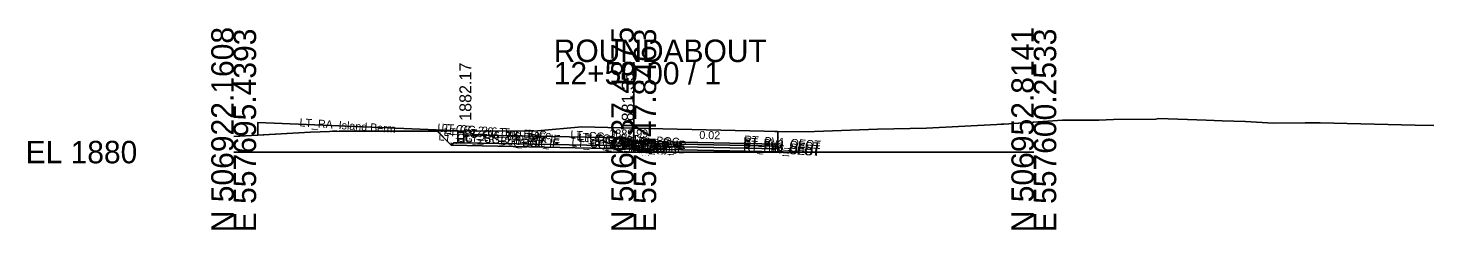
# Model space of a CAD drawing. Extents: x -36 to 140, y -10 to 2515.
# Drawn here: x -35.7 to 140, y 2490.3 to 2515.5 of the extents above; entities that cross this region are included whole.
import ezdxf

# ---------------------------------------------------------------- set-up
doc = ezdxf.new("R2010")
doc.units = 0
for name, color, linetype in [('Default', 7, 'Continuous'), ('Exist Cross Section Cell', 7, 'Continuous'), ('Exist XS Center Line Elevation Label', 7, 'Continuous'), ('Exist XS Ground Line', 7, 'Continuous'), ('Prop CMT Conc Surface', 7, 'Continuous'), ('Prop CMT Pvmt Course 1', 7, 'Continuous'), ('Prop CMT Pvmt Course 1 CG', 7, 'Continuous'), ('Prop CMT Pvmt Course 2', 7, 'Continuous'), ('Prop CMT Pvmt Course 3', 7, 'Continuous'), ('Prop CMT Pvmt Course 4', 7, 'Continuous'), ('Prop CMT Slope Grass', 7, 'Continuous'), ('Prop CMT Subgrade Earthwork', 7, 'Continuous'), ('Prop Conc 4in Sidewalk', 7, 'Continuous'), ('Prop XS Earthwork Shape', 7, 'Continuous'), ('Prop XS Finish Grade Earthwork', 7, 'Continuous'), ('Prop XS Hydro Elevations', 7, 'Continuous'), ('Typical Structure Recommendation Sheet 1 CELL', 7, 'Continuous')]:
    doc.layers.add(name, color=color, linetype=linetype)

msp = doc.modelspace()

# ---------------------------------------------------------------- linework, layer by layer
at = {"layer": 'Exist Cross Section Cell'}
for p, q in [((40, 2500), (40, 2511.23)), ((-10, 2500), (40, 2500)), ((40, 2500), (90, 2500))]:
    msp.add_line(p, q, dxfattribs=at)
at = {"layer": 'Exist XS Ground Line'}
for p, q in [((86.24, 2503.5), (93.59, 2503.98)), ((93.59, 2503.98), (98.14, 2503.98)), ((98.14, 2503.98), (99.96, 2504.06)), ((99.96, 2504.06), (105.26, 2504.12)), ((105.26, 2504.12), (105.57, 2504.18)), ((105.57, 2504.18), (109.2, 2504.05)), ((109.2, 2504.05), (111.56, 2503.96)), ((111.56, 2503.96), (113.54, 2503.88)), ((113.54, 2503.88), (116.46, 2503.8)), ((116.46, 2503.8), (119.9, 2503.59)), ((119.9, 2503.59), (123.93, 2503.63)), ((123.93, 2503.63), (125.77, 2503.65)), ((125.77, 2503.65), (137.66, 2503.35)), ((70.45, 2502.84), (76.6, 2502.97)), ((85.39, 2503.44), (85.9, 2503.48)), ((85.9, 2503.48), (86.24, 2503.5)), ((137.66, 2503.35), (140, 2503.31))]:
    msp.add_line(p, q, dxfattribs=at)
msp.add_lwpolyline([(-10, 2501.94), (-0.39, 2502.47), (3.19, 2502.62), (27.96, 2502.63), (33.49, 2503.14), (40, 2502.99), (56.29, 2502.61), (58.94, 2502.54), (62.57, 2502.57), (70.45, 2502.84), (76.6, 2502.97), (85.39, 2503.44), (85.9, 2503.48), (86.24, 2503.5), (90, 2503.74)], dxfattribs=at)
at = {"layer": 'Prop CMT Conc Surface'}
for p, q in [((18.65, 2502.45), (18, 2502.67)), ((18, 2502.67), (18, 2501.67)), ((18.75, 2501.67), (18.75, 2502.31)), ((17.2, 2500.87), (17.5, 2501.17)), ((18, 2501.17), (17.5, 2501.17)), ((18, 2501.67), (18.75, 2501.67)), ((18, 2501.67), (18, 2501.17)), ((18, 2501.17), (18.75, 2501.17)), ((18.75, 2501.17), (18.75, 2501.67)), ((38.5, 2500.76), (38.5, 2501.76)), ((39.18, 2501.53), (38.5, 2501.76)), ((40, 2500.76), (38.5, 2500.76)), ((38.59, 2500.97), (38.51, 2500.95)), ((38.51, 2500.95), (38.55, 2500.84)), ((38.55, 2500.84), (38.59, 2500.97)), ((38.64, 2501.59), (38.56, 2501.59)), ((38.56, 2501.59), (38.64, 2501.5)), ((38.64, 2501.5), (38.64, 2501.59)), ((38.84, 2501.28), (38.88, 2501.13)), ((38.92, 2501.22), (38.84, 2501.28)), ((38.88, 2501.13), (38.92, 2501.22)), ((39.15, 2500.99), (39.24, 2500.94)), ((39.18, 2500.86), (39.15, 2500.99)), ((39.24, 2500.94), (39.18, 2500.86)), ((39.25, 2501.43), (39.25, 2501.44)), ((40, 2501.34), (39.34, 2501.34)), ((39.5, 2500.95), (39.43, 2500.94)), ((39.43, 2500.94), (39.47, 2500.83)), ((39.47, 2500.83), (39.5, 2500.95)), ((39.76, 2501.27), (39.8, 2501.12)), ((39.84, 2501.21), (39.76, 2501.27)), ((39.8, 2501.12), (39.84, 2501.21)), ((40, 2501.34), (40, 2500.76)), ((40, 2500.76), (40, 2501.33))]:
    msp.add_line(p, q, dxfattribs=at)
msp.add_lwpolyline([(40, 2500.76), (40, 2501.35)], dxfattribs=at)
msp.add_lwpolyline([(40, 2500.76), (40, 2501.35)], dxfattribs=at)
for centre in [(38.57, 2501.35), (38.58, 2501.24), (38.62, 2500.87), (38.64, 2501.08), (38.71, 2501.67), (38.73, 2501.22), (38.73, 2501.39), (38.76, 2500.83), (38.78, 2501.09), (38.79, 2501), (38.85, 2501.34), (38.92, 2501.48), (38.92, 2501.06), (39.02, 2501.21), (39.02, 2500.81), (39.04, 2500.93), (39.04, 2501.34), (39.06, 2501.5), (39.07, 2501.07), (39.11, 2501.25), (39.23, 2501.28), (39.25, 2501.18), (39.27, 2500.8), (39.34, 2500.94), (39.34, 2500.79), (39.36, 2501.02), (39.37, 2501.26), (39.38, 2501.23), (39.5, 2501.22), (39.54, 2500.85), (39.56, 2501.06), (39.65, 2501.21), (39.68, 2500.81), (39.69, 2501.08), (39.71, 2500.98), (39.77, 2501.32), (39.84, 2501.05), (39.94, 2501.19), (39.94, 2500.79), (39.96, 2500.91), (39.99, 2501.05)]:
    msp.add_circle(centre, 0.00635, dxfattribs=at)
for centre, radius, start, end in [((18.6, 2502.31), 0.146, 0, 71.5651), ((38.53, 2500.76), 0.00635, 27.0386, 154.2416), ((39.15, 2501.44), 0.0937, 0, 71.5651), ((39.34, 2501.43), 0.0937, 180, 270)]:
    msp.add_arc(centre, radius, start, end, dxfattribs=at)
at = {"layer": 'Prop CMT Pvmt Course 1'}
for points in [[(40, 2501.35), (58, 2500.99)], [(40, 2501.1), (40, 2501.35)], [(40, 2501.1), (40, 2501.35)], [(40, 2501.09), (40, 2501.34)], [(58, 2500.74), (40, 2501.1)], [(58, 2500.99), (58, 2500.74)], [(58, 2500.99), (58, 2500.74)], [(58, 2500.85), (58, 2500.6)]]:
    msp.add_lwpolyline(points, dxfattribs=at)
at = {"layer": 'Prop CMT Pvmt Course 1 CG'}
msp.add_lwpolyline([(58, 2500.15), (58, 2500.4)], dxfattribs=at)
at = {"layer": 'Prop CMT Pvmt Course 2'}
for points in [[(40, 2500.76), (40, 2501.1)], [(40, 2501.1), (58, 2500.74)], [(40, 2500.76), (40, 2501.1)], [(40, 2500.76), (40, 2501.09)], [(58, 2500.4), (40, 2500.76)], [(58, 2500.74), (58, 2500.4)], [(58, 2500.6), (58, 2500.26)]]:
    msp.add_lwpolyline(points, dxfattribs=at)
at = {"layer": 'Prop CMT Pvmt Course 3'}
for points in [[(40, 2500.76), (58, 2500.4)], [(58, 2500.4), (58, 2500.05)], [(58, 2500.4), (58, 2500.07)]]:
    msp.add_lwpolyline(points, dxfattribs=at)
at = {"layer": 'Prop CMT Pvmt Course 4'}
for points in [[(40, 2500.43), (40, 2500.43)], [(40, 2500.43), (40, 2500.43)], [(40, 2500.42), (40, 2500.42)], [(58, 2500.07), (58, 2500.07)], [(58, 2500.07), (58, 2500.07)]]:
    msp.add_lwpolyline(points, dxfattribs=at)
at = {"layer": 'Prop CMT Slope Grass'}
msp.add_line((-7, 2502.11), (-7, 2503.67), dxfattribs=at)
msp.add_lwpolyline([(15.29, 2502.78), (-7, 2503.67)], dxfattribs=at)
at = {"layer": 'Prop CMT Subgrade Earthwork'}
for p, q in [((17.2, 2500.87), (15.29, 2502.78)), ((58, 2500.07), (58, 2502.56)), ((17.2, 2500.87), (38.49, 2500.42)), ((38.49, 2500.42), (39.98, 2500.42)), ((39.98, 2500.42), (58, 2500.05))]:
    msp.add_line(p, q, dxfattribs=at)
at = {"layer": 'Prop Conc 4in Sidewalk'}
for p, q in [((18.75, 2502.17), (18.75, 2501.17)), ((18.75, 2502.17), (38.5, 2501.76)), ((18.75, 2501.17), (38.5, 2500.76))]:
    msp.add_line(p, q, dxfattribs=at)
at = {"layer": 'Prop XS Earthwork Shape'}
for points in [[(-7, 2502.11), (-7, 2503.67), (15.29, 2502.78), (15.44, 2502.62), (3.19, 2502.62), (-0.39, 2502.47)], [(39.98, 2500.42), (58, 2500.05), (58, 2502.56), (56.29, 2502.61), (40, 2502.99), (33.49, 2503.14), (27.96, 2502.63), (15.44, 2502.62), (17.2, 2500.87), (38.49, 2500.42)]]:
    msp.add_lwpolyline(points, close=True, dxfattribs=at)
at = {"layer": 'Prop XS Finish Grade Earthwork'}
msp.add_line((15.29, 2502.78), (18, 2502.67), dxfattribs=at)

# ---------------------------------------------------------------- texts
at = {"layer": 'Default'}
msp.add_text('-', height=0.0001, dxfattribs=at).set_placement((0, 2500))
at = {"layer": 'Exist Cross Section Cell'}
for s, p in [('N 506922.1608', (-10, 2490)), ('E 557695.4393', (-7.2, 2490)), ('N 506937.4875', (40, 2490)), ('E 557647.8463', (42.8, 2490)), ('N 506952.8141', (90, 2490)), ('E 557600.2533', (92.8, 2490))]:
    msp.add_text(s, height=2.8, rotation=90, dxfattribs=at).set_placement(p)
for s, p in [('ROUNDABOUT', (30, 2511.23)), ('12+50.00 / 1', (30, 2508.43)), ('EL 1880', (-36, 2498.6))]:
    msp.add_text(s, height=2.8, dxfattribs=at).set_placement(p)
at = {"layer": 'Exist XS Center Line Elevation Label'}
msp.add_text('1882.99', height=1, dxfattribs=at).set_placement((36.96, 2501.82))
at = {"layer": 'Prop XS Hydro Elevations'}
for s, height, rotation, p in [('1882.17', 1.5, 90, (19.71, 2503.9)), ('1881.35', 1.5, 90, (40, 2502.72)), ('0.02', 1, 358.8542, (48.19, 2501.64))]:
    msp.add_text(s, height=height, rotation=rotation, dxfattribs=at).set_placement(p)
at = {"layer": 'Typical Structure Recommendation Sheet 1 CELL'}
for s, p in [('LT_RA_Island Berm', (-1.8, 2503.22)), ('LT_CG_2-6_Top_BOC', (15.43, 2502.56)), ('LT_CG_2-6_Bot_BOC', (15.57, 2501.47)), ('LT_CG_2-6_Top_Face', (15.94, 2502.55)), ('LT_CG_2-6_Top_Gut', (16.21, 2502.04)), ('LT_CG_2-6_Top_IE', (18.8, 2501.95)), ('LT_CG_2-6_Bot_IE', (18.94, 2501.36)), ('LT_CG_1-6_Top_BOC', (32.05, 2501.71)), ('LT_CG_1-6_Top_Face', (32.82, 2501.46)), ('LT_CG_1-6_Top_Gut', (33.09, 2501.28)), ('LT_CG_1-6_Top_IE', (34.43, 2501.23)), ('LT_MI_BOC', (35.04, 2500.92)), ('RT_PV1_OEOT', (53.78, 2501.08)), ('LT_CG_1-6_Bot_BOC', (32.19, 2500.71)), ('LT_CG_1-6_Bot_IE', (34.57, 2500.64)), ('LT_PV2_PGL', (36.35, 2500.85)), ('LT_PV3_PGL', (36.35, 2500.52)), ('LT_PV4_PGL', (36.35, 2500.18)), ('LT_Sub_PGL', (36.38, 2500.18)), ('RT_PV2_OEOT', (53.66, 2500.84)), ('RT_PV3_OEOT', (53.66, 2500.5)), ('RT_PV4_OEOT', (53.66, 2500.17)), ('RT_Sub_OEOT', (53.68, 2500.17))]:
    msp.add_text(s, height=1, rotation=356, dxfattribs=at).set_placement(p)

doc.saveas('drawing.dxf')
